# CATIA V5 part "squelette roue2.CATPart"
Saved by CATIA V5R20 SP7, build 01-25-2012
Part number: squelette roue2
Publications: "Plan.1", "Plan.2", "Plan.3", "Point.1", "Plan.4", "Droite.1", "Point.2", "Droite.2", "Droite.3", "Point.4", "Point.3", "Point.5", "Point.6", "Point.7", "Droite.4", "position horizontale du pivot2", "Point.8", "Point.9", "Point.10", "rayon1 du tube2", "rayon2 du tube2", "Plan.5", "haut du support de la petale", "longeur du support de la petale", "largeur du support de la petale", "longueur de chanfrain", "Droite.7", "Droite.6", "Droite.5", "Point.11", "distance entre le haut et le pivot plus haut", "position verticale du pivot plus haut", "demi_largeur de la partie verticale", "demi_largeur de la partie horizontale", "demi_distance entre les oreilles", "epaisseur de l'oreille", "rayon de la liaison du petale", "Point.12", "Droite.8", "rayon plus grande de la boite", "rayon plus petite de la boite", "epaisseur de la boite", "position verticale de la liaison du petale", "position horizondale de la liaison du petale"
Bounding box of the stored display mesh (mm): x -60 to 50, y -40 to 40, z 0 to 460
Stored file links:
  D:\thinkmotion-MPB\Dropbox\Pack 1 sylvain\CFAO_2010_yyang\yyang\CFAO_2010_yyang\squelette roue2.CATPart
  D:\thinkmotion-MPB\Dropbox\Pack 1 sylvain\CFAO_2010_yyang\yyang\CFAO_2010_yyang\yyang.CATProduct
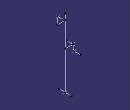
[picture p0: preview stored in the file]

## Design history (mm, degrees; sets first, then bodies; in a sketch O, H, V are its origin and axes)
Parameters
  `position horizontale du pivot2` = 50 mm
  `rayon1 du tube2` = 21 mm
  `rayon2 du tube2` = 24 mm
  `haut du support de la petale` = 275 mm
  `longeur du support de la petale` = 180 mm
  `largeur du support de la petale` = 100 mm
  `longueur de chanfrain` = 35 mm
  `distance entre le haut et le pivot plus haut` = 10 mm
  `position verticale du pivot plus haut` = 50 mm
  `longeur de ligne verticale ` = 47.5 mm
  `demi_largeur de la partie verticale` = 10 mm
  `demi_largeur de la partie horizontale` = 12.5 mm
  `demi_distance entre les oreilles` = 15 mm
  `epaisseur de l'oreille` = 3 mm
  `position verticale de la liaison du petale` = -45 mm
  `position horizondale de la liaison du petale` = -10 mm
  `rayon de la liaison du petale` = 10 mm
  `rayon plus grande de la boite` = 35 mm
  `rayon plus petite de la boite` = 15 mm
  `epaisseur de la boite` = 7.5 mm
External parameters (linked from other documents)
  `External.Longueur du tube` = 450 mm
  `External.position vertical du pivot1` = 250 mm
  `External.Longueur du roue` = 54 mm
  `External.epaisseur du roue` = 32 mm
  `External.rayon1 de l'antiboue` = 30 mm
  `External.rayon2 de l'antiboue` = 25 mm
  `External.rayon de l'axe` = 5 mm
Body1 (main body)
  Plane1: type Offset, RefPlane xy-plane, Offset 0
  Plane2: type Offset, RefPlane yz-plane, Offset 0
  Plane3: type Offset, RefPlane zx-plane, Offset 0
  Point1: (0, 0, 0)
  Plane4: type Offset, RefPlane Plane1, Offset 450 {= `External.Longueur du tube`}
  Line1: type PtDir, LineFirstUpto Plane4, RefPoint Point1, Direction (0, 0, 1), Start 0, End 0
  Point2: (-50 {= -`position horizontale du pivot2`}, 0, 250 {= `External.position vertical du pivot1`})
  Line2: type PtDir, LineFirstUpto Line1, RefPoint Point2, Direction (1, 0, 0), Start 0, End 0
  Line3: type PtDir, RefPoint Point2, Direction (0, 1, 0), Start 0, End 40
  Point3: (0, 0, 54 {= `External.Longueur du roue`})
  Point4: (0, 0, -54 {= -`External.Longueur du roue`})
  Point5: (0, 16 {= `External.epaisseur du roue`/2}, 0)
  Point6: (0, 0, 84 {= `External.rayon1 de l'antiboue`+`External.Longueur du roue`})
  Point7: (0, 0, 79 {= `External.rayon2 de l'antiboue` +`External.Longueur du roue`})
  Line4: type PtDir, RefPoint Point1, Direction (0, 1, 0), Start -40, End 40
  Point8: (0, 0, 5 {= `External.rayon de l'axe`})
  Point9: (21 {= `rayon1 du tube2`}, 0, 450 {= `External.Longueur du tube`})
  Point10: (24 {= `rayon2 du tube2`}, 0, 450 {= `External.Longueur du tube`})
  Plane5: type Offset, RefPlane Plane1, Offset 275 {= `haut du support de la petale`}
  Point11: (50 {= `position verticale du pivot plus haut`}, 0, 460 {= `distance entre le haut et le pivot plus haut`+`External.Longueur du tube`})
  Line5: type PtDir, RefPoint Point11, Direction (0, 0, 1), Start 0, End 47.5 {= `longeur de ligne verticale `}
  Line6: type PtDir, LineFirstUpto Line1, RefPoint vertex of Line5, Direction (1, 0, 0), Start 0, End 0
  Line7: type PtDir, RefPoint Point11, Direction (0, 1, 0), Start 0, End 40
  Point12: (-10 {= `position horizondale de la liaison du petale`}, 0, -45 {= `position verticale de la liaison du petale`}), relative to Point2
  Line8: type PtDir, RefPoint Point12, Direction (0, 1, 0), Start 0, End 40
  Line9: type PtPt, FirstPoint Point2, SecondPoint Point12
Relations
  Point2.X = - (deactivated)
